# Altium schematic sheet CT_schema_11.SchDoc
size 147 x 119 mm
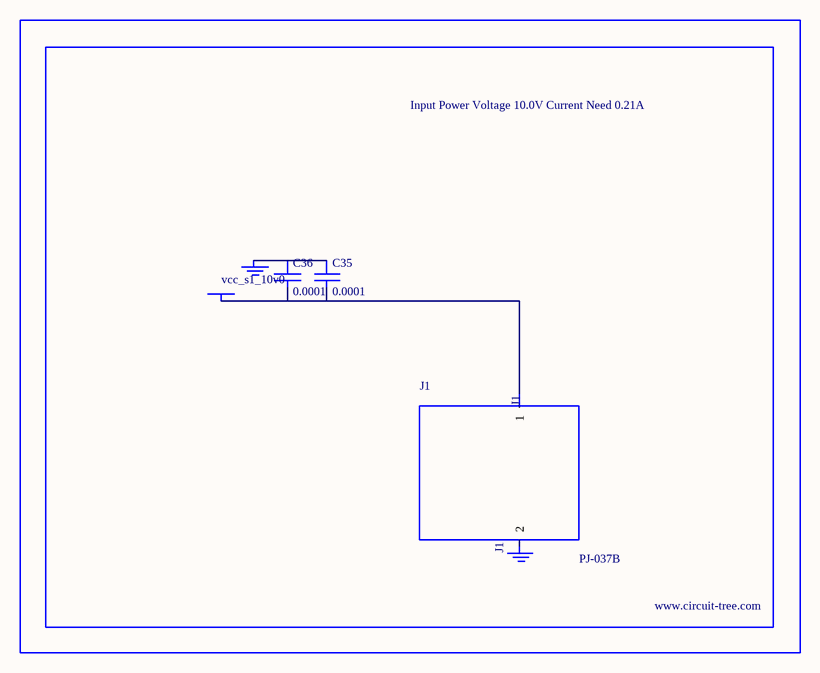
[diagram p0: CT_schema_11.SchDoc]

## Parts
BORDER10  (no value)
C35  0.0001  [EXV-9H]
C36  0.0001  [EXV-9H]
GND_INSTANCE_10_0  (no value)
GND_INSTANCE_10_1  (no value)
J1  PJ-037B  [PJ-037B_PACKAGE]
POWER_INSTANCE_10_0  vcc_s1_10v0

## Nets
NetC35_1: C35.1 C36.1 GND_INSTANCE_10_0.0(GND)
NetC35_2: C35.2 C36.2 J1.1 POWER_INSTANCE_10_0.0(PWR)

Not connected (* = marked no-connect by the designer): GND_INSTANCE_10_1 0(GND); J1 2

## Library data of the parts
BORDER10 = BORDER_PAGE10
C35 C36 = EDK107M035A9HAA
GND_INSTANCE_10_0 GND_INSTANCE_10_1 = GND
POWER_INSTANCE_10_0 = PWR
